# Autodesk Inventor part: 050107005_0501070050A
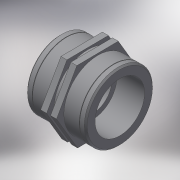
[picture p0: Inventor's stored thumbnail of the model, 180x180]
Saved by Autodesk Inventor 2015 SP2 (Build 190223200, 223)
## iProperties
Created: 2017-05
Part Number: 050107005_0501070050A
Material: Generic
Description: PLASSON SOCKET PP 1/2"-1/2"
Document SubType Name: Modeling
Designer: KIM
Density: 1 g/cm^3
Appearance: Default
Author: KIM
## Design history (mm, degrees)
derived "050107.ipt"
feature "Solid1::050107.ipt"
tag "TaggingFeature1"
body "Solid1"
other parameters: "d0" = 39, "d2" = 18.631, "d3" = 17, "d6" = 28.5, "d7" = 14.9048, "d14" = 0, "d15" = 0.55893, "d18" = 3.9, "d19" = 1.3, "d20" = 0.5, "d21" = 0.5, "d22" = 28.5, "Rp_" = 18.631, "H_" = 39, "l_2" = 17
